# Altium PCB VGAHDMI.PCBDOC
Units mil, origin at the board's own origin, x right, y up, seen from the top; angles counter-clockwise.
Board outline 1870 x 1740 mil, 2 copper layers (Top Layer, Bottom Layer); 8 components, 366 nets, 72 pads, 2 vias.
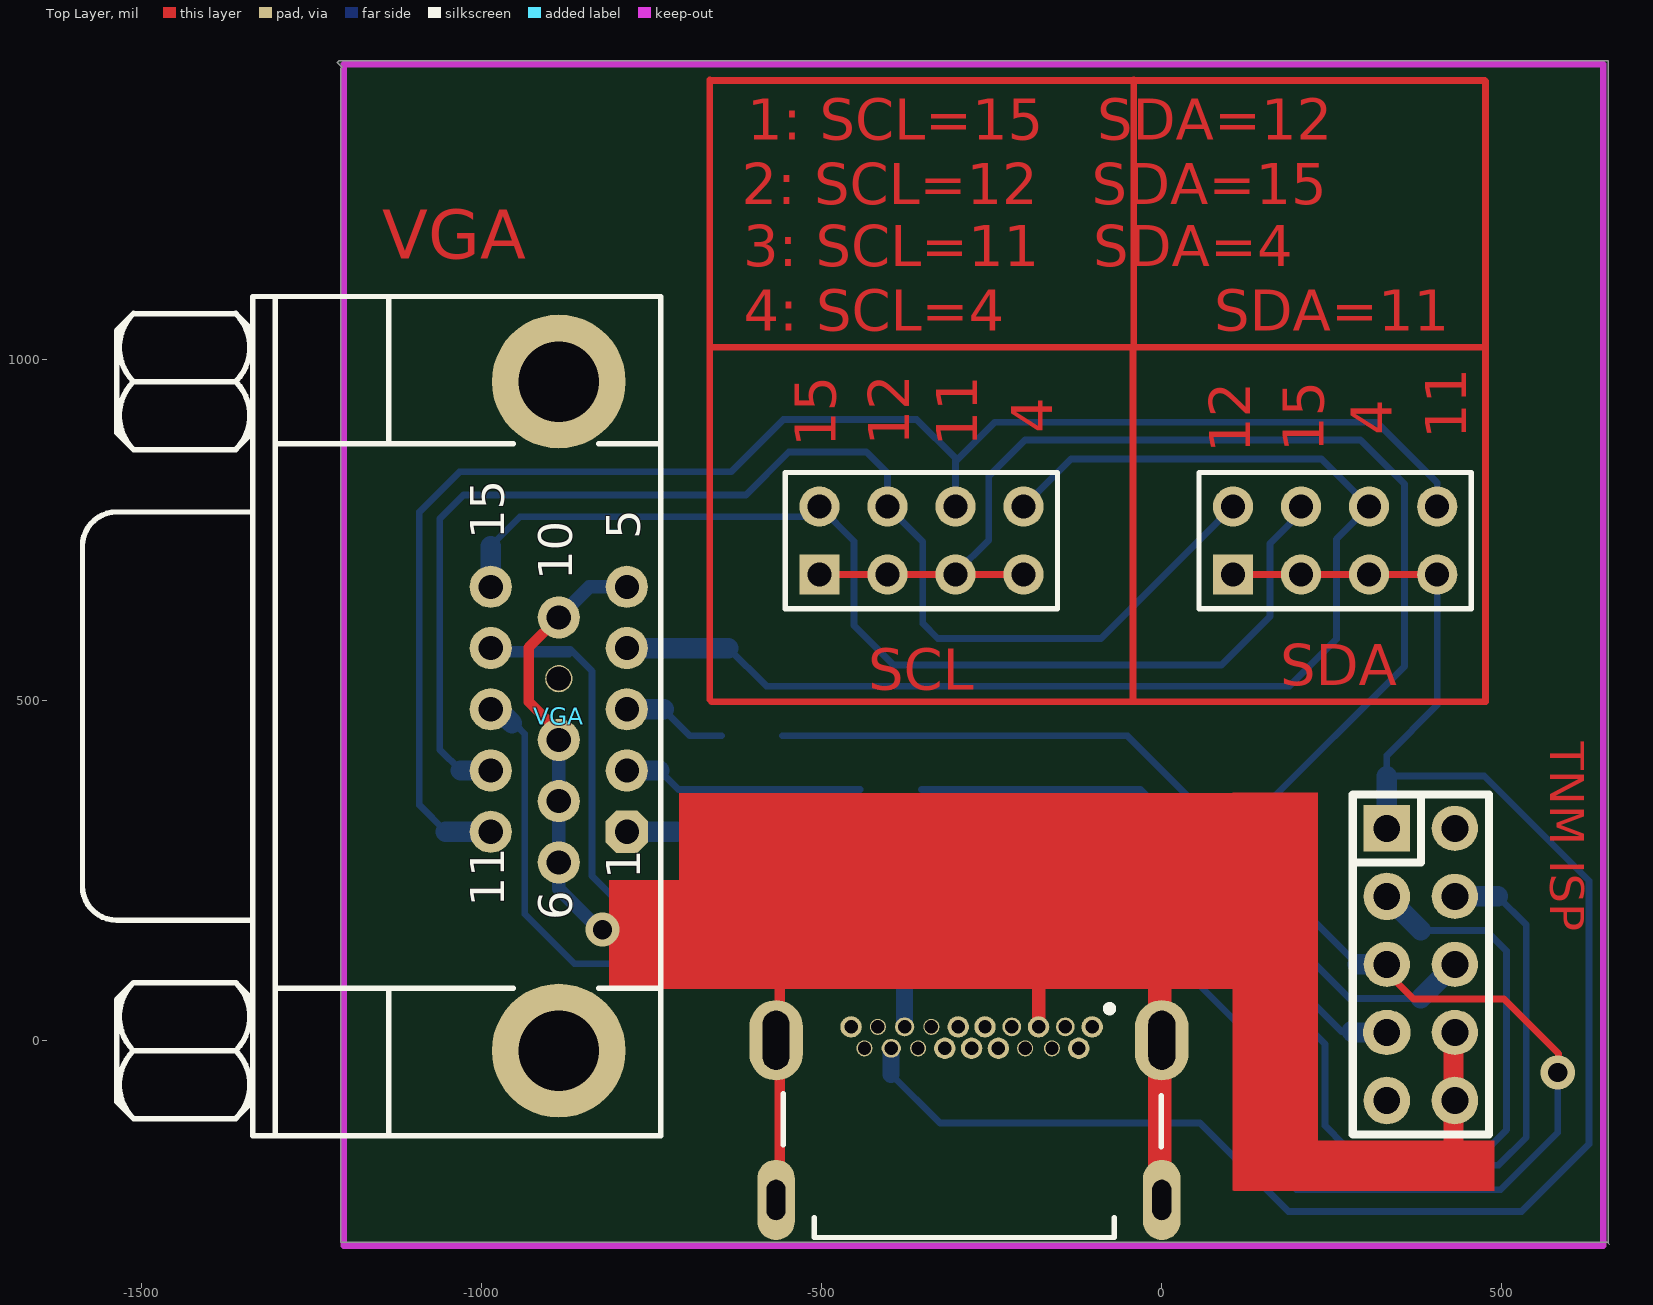
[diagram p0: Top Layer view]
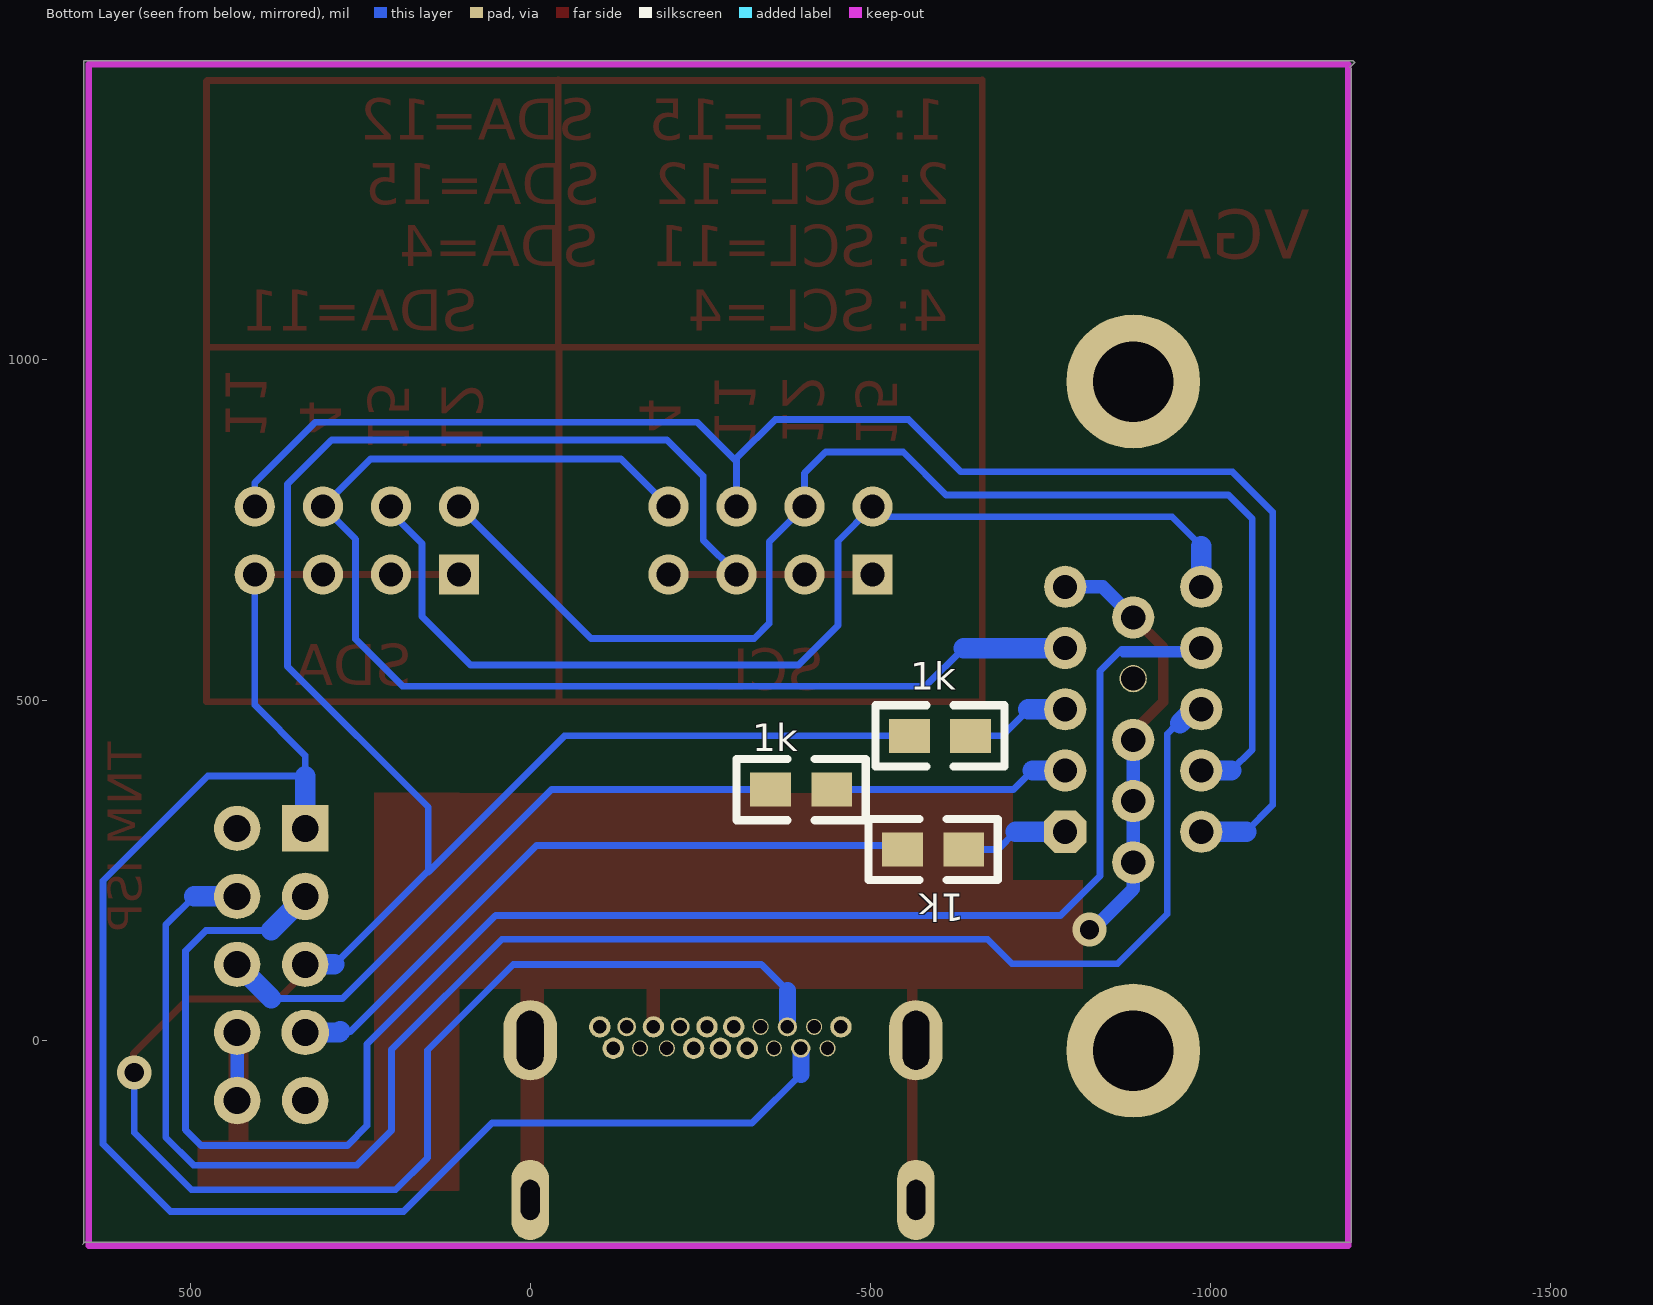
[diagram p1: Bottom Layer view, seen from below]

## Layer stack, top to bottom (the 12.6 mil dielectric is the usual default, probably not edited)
Top Layer: signal copper 1.4
Dielectric: core 12.6, FR-4, Dk 4.8
Bottom Layer: signal copper 1.4

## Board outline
-1212,1437 -1209,1440 656,1440 656,-298 658,-300 655,-297 -1207,-297 -1207,1428 -1205,1430

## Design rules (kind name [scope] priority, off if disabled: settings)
Clearance [All] p1: gap=9
FabricationTestPointUsage TestPointUsage [All] p1: valid=0 allowmultiple=FALSE
FabricationTestpoint Testpoint [(IsPad And (OnTopLayer Or OnBottomLayer))] p1: side=3 testpointundercomponent=TRUE minsize=40 maxsize=100 preferedsize=60 minholesize=0 maxholesize=40 preferedholesize=32 testpointgrid=1 allowsidetop=TRUE allowsidebottom=TRUE usegrid=TRUE gridtolerance=0.01
FanoutControl Fanout_Small [All] p1 off: bgadir=Out bgaviamode=Centered fanoutstyle=Auto fanoutdirection=Alternating viagrid=1 // Protel DXP Scope 1 Expression Was: (CompPinCount < 5)   Fanout_Small (Default Rule)
FanoutControl Fanout_Default [All] p2: bgadir=Out bgaviamode=Centered fanoutstyle=Auto fanoutdirection=Alternating viagrid=1 // Fanout_Default (Default Rule)
FanoutControl Fanout_SOIC [All] p3 off: bgadir=Out bgaviamode=Centered fanoutstyle=Auto fanoutdirection=Alternating viagrid=1 // Protel DXP Scope 1 Expression Was: IsSOIC   Fanout_SOIC (Default Rule)
FanoutControl Fanout_BGA [All] p4 off: bgadir=Out bgaviamode=Centered fanoutstyle=Auto fanoutdirection=Alternating viagrid=1 // Protel DXP Scope 1 Expression Was: IsBGA   Fanout_BGA (Default Rule)
FanoutControl Fanout_LCC [All] p5 off: bgadir=Out bgaviamode=Centered fanoutstyle=Auto fanoutdirection=Alternating viagrid=1 // Protel DXP Scope 1 Expression Was: IsLCC   Fanout_LCC (Default Rule)
PolygonConnect PolygonVia [IsVia] p1: connectstyle=Direct reliefconductorwidth=10 reliefentries=4 polygonreliefangle="90 Angle"
PolygonConnect [All] p2: connectstyle=Relief reliefconductorwidth=10 reliefentries=4 polygonreliefangle="90 Angle"
RoutingCorners [All] p1: cornerstyle=Round minsetback=100 maxsetback=100
RoutingLayers [All] p1: top layer_v5=FALSE bottom layer_v5=FALSE
RoutingVias [All] p1: holewidth=28 width=50 viastyle="Through Hole" minholewidth=28 minwidth=50 maxholewidth=28 maxwidth=50
SilkscreenOverComponentPads [All] p1: minsilkscreentomaskgap=10
SolderMaskExpansion [All] p1: expansion=4
Width [All] p1: maxlimit=150 minlimit=1 preferedwidth=10
18 further rules are at their usual default settings.

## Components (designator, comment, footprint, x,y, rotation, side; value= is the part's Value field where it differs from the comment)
1k "4.7" 0805 -557.25,447.46 r180 bottom
1k "4.7" 0805 -443.25,368.46 r0 bottom
1k "4.7" 0805 -637.25,280.46 r0 bottom
VGA "Comment" DB15FLC -786.25,306.46 r90 top
? "Comment" HDMI/SM0.4-4H19 -290.25,-250.54 r270 top
? "Comment" HDR2X4 -503.25,684.46 r0 top
? "Comment" HDR2X4 104.75,684.46 r0 top
? "2.2k" IDC10 330.75,311.46 r270 top

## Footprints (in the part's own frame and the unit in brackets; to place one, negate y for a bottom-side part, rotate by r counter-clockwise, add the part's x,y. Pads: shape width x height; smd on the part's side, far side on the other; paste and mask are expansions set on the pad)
0805 [mil]
  rect 60x50 smd: 1(0,0) 2(90,0)
  silkscreen extent -50,-45 140,45
DB15FLC [mil]
  oct 62x62 hole 35.43: 1(0,0)
  round 62 hole 35.43: 2(90,0) 3(180,0) 4(270,0) 5(360,0) 6(-45,100) 7(45,100) 8(135,100) 10(315,100) 11(0,200) 12(90,200) 13(180,200) 14(270,200) 15(360,200)
  round 40 hole 35.43: 9(225,100)
  round 196.67 hole 118.33: BO1(-321.67,100) BO2(661.67,100)
  silkscreen extent -447,-50 787,800
HDMI/SM0.4-4H19 [mm] "3168 Series HDMI Type C, Female, Right-Angle, SMT"
  round 0.8 hole 0.5 unplated: 1(-6.864,4.772) 2(-6.064,4.272) 5(-6.864,2.772) 8(-6.064,1.272) 9(-6.864,0.772) 10(-6.064,0.272) 11(-6.864,-0.228) 12(-6.064,-0.728) 19(-6.864,-4.228)
  round 0.7 hole 0.5 unplated: 3(-6.864,3.772) 7(-6.864,1.772)
  round 0.6 hole 0.5 unplated: 4(-6.064,3.272) 6(-6.064,2.272) 13(-6.864,-1.228) 14(-6.064,-1.728) 17(-6.864,-3.228) 18(-6.064,-3.728)
  oval 0.7x0.72 hole 0.5 unplated: 15(-6.864,-2.228) 16(-6.064,-2.728)
  oval 3x2 hole 1 slot 2.2 at 0 deg: MH1(-6.364,-7.028) MH4(-6.364,7.372)
  oval 3x1.4 hole 0.7 slot 1.5 at 0 deg: MH2(-0.404,-7.028) MH3(-0.404,7.372)
  silkscreen extent -7.67,-6.76 1,7.35
HDR2X4 [mm] "Connector; Header; 4x2 Position"
  rect 1.5x1.5 hole 0.9: 1(0,0)
  round 1.5 hole 0.9: 2(0,2.54) 3(2.54,0) 4(2.54,2.54) 5(5.08,0) 6(5.08,2.54) 7(7.62,0) 8(7.62,2.54)
  silkscreen extent -1.27,-1.27 8.89,3.81
IDC10 [mil]
  rect 68x68 hole 39.37: 1(0,0)
  oval 66x68 hole 39.37: 2(0,100) 4(100,100) 5(200,0) 6(200,100) 8(300,100)
  oval 70x68 hole 39.37: 3(100,0) 9(400,0) 10(400,100)
  oval 66x70 hole 39.37: 7(300,0)
  silkscreen extent -50,-50 450,150

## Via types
v1: diameter 50, hole 28, Top Layer to Bottom Layer, 2 vias

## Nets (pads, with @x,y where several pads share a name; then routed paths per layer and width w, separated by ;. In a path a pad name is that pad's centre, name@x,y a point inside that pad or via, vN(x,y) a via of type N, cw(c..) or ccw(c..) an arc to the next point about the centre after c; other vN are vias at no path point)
5V: 
12+: 
+3.3V: 
+5: 
AD0: 
AD1: 
AD2: 
AD3: 
AD4: 
AD5: 
AD6: 
AD7: 
ALE: 
AREF: 
BLUE: 1k.2@-647.25,447.46 VGA.3 | length 155.2
  Bottom Layer w10: -732.25,486.46 -693.25,447.46 1k.2@-647.25,447.46
  Bottom Layer w30: VGA.3 -732.25,486.46
CANA: 
CANEN: 
CANH: 
CANL: 
CASE: 
COMP7: 
COMP10: 
COMP14: 
COMP15: 
CTL0: 
CTL1: 
CTL2: 
D12X1: 
D12X2: 
DEBUG: 
DELYF: 
DLYEN: 
DM: 
DONE: 
DP: 
EMPTY: 
FD0: 
FD1: 
FD2: 
FD3: 
FD4: 
FD5: 
FD6: 
FD7: 
FIFOADD0: 
FULL: 
G: 1k.1@-443.25,368.46 VGA.2 | length 354.6
  Bottom Layer w10: -738.25,396.46 -710.25,368.46 1k.1@-443.25,368.46
  Bottom Layer w30: VGA.2 -738.25,396.46
GND: ?.5@-181.1,19.69 ?.8@430.75,11.46 ?.10@430.75,-88.54 ?.MH1 ?.MH2 ?.MH3 ?.MH4 VGA.5 VGA.6 VGA.7 VGA.8 VGA.10 | length 962.7
  Top Layer w10: VGA.8 VGA.8@-886.25,453.46
  Top Layer w15: VGA.8@-886.25,453.46 -930.25,497.46 -930.25,577.46 VGA.10
  Top Layer w20: ?.5@-181.1,19.69 -181.1,76.26
  Top Layer w30: 428.75,-174.54 ?.8@428.75,-11.54
  Bottom Layer w10: v1@-828.25,164.46 v1@-821.25,164.46
  Bottom Layer w20: VGA.8 VGA.7 VGA.6 -886.25,222.46 v1@-828.25,164.46 ; VGA.10 -841.25,666.46 VGA.5 ; ?.10@430.75,-88.54 ?.8@430.75,11.46
  other v1: -822.25,162.46
GNDISO: 
GREEN: 1k.2@-353.25,368.46 ?.6@430.75,111.46 | length 932.9
  Bottom Layer w10: 1k.2@-353.25,368.46 -31.25,368.46 275.75,61.46 381.75,61.46
  Bottom Layer w30: 380.75,61.46 ?.6@430.75,111.46
H: ?.4@430.75,211.46 VGA.13 | length 2504.2
  Bottom Layer w10: VGA.13 VGA.13@-973.46,486.46 ; -948,462 -936.25,450.25 -936.25,185.46 -863.25,112.46 -708.25,112.46 -672.25,148.46 41.75,148.46 203.75,-13.54 203.75,-132.54 254.75,-183.54 494.75,-183.54 535.75,-142.54 535.75,169.46 493.75,211.46
  Bottom Layer w30: VGA.13@-979.25,490.25 -955,466 ; ?.4@430.75,211.46 493.75,211.46
HSYNC: 
IGNITION: 
ISPCLKI: 
ISPEN: 
ISPHIN1: 
ISPIN1: 
ISPIN6: 
ISPOUT1: 
ISPOUT4: 
ISPOUT6: 
ISPPDII: 
ISPRST: 
ISPSCK: 
ISPSDI: 
ISPSDO: 
LED: 
MCLR: 
MCU_CLK: 
MCU_RESET: 
MISO: 
MOSI: 
N01: 
N02: 
N03: 
N04: 
N05: 
N5: 
N06: 
N6: 
N07: 
N7: 
N08: 
N8: 
N09: 
N10: 
N11: 
N12: 
N13: 
N14: 
N15: 
N16: 
N17: 
N18: 
N19: 
N20: 
N21: 
N23: 
N25: 
N26: 
N27: 
N28: 
N29: 
N30: 
N31: 
N32: 
N33: 
N34: 
N35: 
N36: 
N37: 
N38: 
N39: 
N40: 
N41: 
N42: 
N43: 
N44: 
N45: 
N46: 
N47: 
N48: 
N49: 
N66: 
NC4: 
NewNet: 
O4: 
O5: 
O6: 
O7: 
O11: 
O12: 
O13: 
OB1: 
OB2: 
OB3: 
OB4: 
OB5: 
OB6: 
OB7: 
OB8: 
OB9: 
OB10: 
OB11: 
OB12: 
OB13: 
OB14: 
OB15: 
OBD1: 
OBD2: 
OBD3: 
OBD6: 
OBD6S: 
OBD7: 
OBD9: 
OBD10: 
OBD11: 
OBD12: 
OBD13: 
OBD14: 
OBD14S: 
OBD15: 
OE: 
P0: 
P1: 
P2: 
P3: 
P04: 
P4: ?.6@304.75,784.46 ?.8@-203.25,784.46 VGA.4 | length 1875.6
  Bottom Layer w10: -637.25,576.46 -581.25,520.46 187.75,520.46 256.75,589.46 256.75,736.46 304.75,784.46 234.75,854.46 -133.25,854.46 ?.8@-203.25,784.46
  Bottom Layer w30: VGA.4 -637.25,576.46
P05: 
P5: 
P6: 
P7: 
P11: ?.6@-303.25,784.46 ?.8@404.75,784.46 VGA.11 | length 2295
  Bottom Layer w10: -1052.25,306.46 -1091.25,345.46 -1091.25,776.46 -1032.25,835.46 -633.25,835.46 -556.25,912.46 -360.25,912.46 -303.25,855.46 -303.25,850.46 ; ?.6@-303.25,784.46 -303.25,850.46 ; ?.8@404.75,784.46 404.75,819.46 315.75,908.46 -245.25,908.46 -303.25,850.46
  Bottom Layer w30: -1052.25,306.46 VGA.11
P12: ?.2@104.75,784.46 ?.4@-403.25,784.46 VGA.12 | length 1926.3
  Bottom Layer w10: -1030.25,396.46 -1061.25,427.46 -1061.25,766.46 -1026.25,801.46 -611.25,801.46 -548.25,864.46 -434.25,864.46 -403.25,833.46 -403.25,784.46 -351.25,732.46 -351.25,612.46 -329.25,590.46 -89.25,590.46 ?.2@104.75,784.46
  Bottom Layer w30: -1030.25,396.46 VGA.12
P15: ?.2@-503.25,784.46 ?.4@204.75,784.46 VGA.15 | length 1608.6
  Bottom Layer w10: -986.25,726.46 -943.25,769.46 -518.25,769.46 -503.25,784.46 -452.25,733.46 -452.25,609.46 -394.25,551.46 87.75,551.46 159.22,622.94 159.22,729.99 204.75,775.52 ?.4@204.75,784.46
  Bottom Layer w30: VGA.15 -986.25,726.46
PA1: 
PC0: 
PC1: 
PDI: 
PDIH: 
PIN1: 
PIN1HB: 
PIN1LB: 
PIN1SB: 
PIN2: 
PIN2H: 
PIN2HB: 
PIN2LB: 
PIN2SB: 
PIN3: 
PIN4: 
PIN4LB: 
PIN4S: 
PIN4SB: 
PIN5: 
PIN6: 
PIN7: 
PIN8: 
PIN9: 
PIN10: 
PIN11: 
PIN12: 
PIN13: 
PIN14: 
PIN15: 
PIN16: 
PIN17: 
PIN18: 
PIN19: 
PIN20: 
PIN21: 
PIN22: 
PIN23: 
PIN24: 
PIN25: 
PIN26: 
PIN27: 
PIN28: 
PIN29: 
PIN30: 
PIN31: 
PIN31H: 
PIN31HB: 
PIN31I: 
PIN31L: 
PIN32: 
PIN33: 
PIN34: 
PIN35: 
PIN36: 
PIN37: 
PIN38: 
PIN39: 
PIN40: 
PIN41: 
PIN42: 
PIN43: 
PIN44: 
PIN45: 
PIN46: 
PIN47: 
PIN48: 
PKTEND: 
PO4: 
PO5: 
PROGRAM: 
PULH: 
PULL: 
PWM1: 
PWM2: 
PWML1: 
PWML2: 
PWMOUT1: 
PWMOUT2: 
R: 1k.1@-637.25,280.46 VGA.1 | length 159.8
  Bottom Layer w10: -713.25,306.46 -687.25,280.46 1k.1@-637.25,280.46
  Bottom Layer w30: VGA.1 -713.25,306.46
RED: 1k.2@-547.25,280.46 ?.7@330.75,11.46 | length 984.9
  Bottom Layer w10: 1k.2@-532.25,286.46 -9.25,286.46 264.21,13 279,13
  Bottom Layer w30: 279,13 280.54,11.46 ?.7@338.75,11.46
RELCAN: 
RESET: 
RLCAN: 
RST: 
RST1: 
RST2: 
RST_SEL: 
RST_SELN: 
RSTF: 
RX: 
RX_K: 
RXD: 
RXD1: 
RXI: 
RXIN: 
RXK: 
SCK: 
SCK1: 
SCKF: 
SCKH: 
SCKI: 
SCL1: 
SCL_BLU: 1k.1@-557.25,447.46 ?.1@-503.25,684.46 ?.3@-403.25,684.46 ?.5@330.75,111.46 ?.5@-303.25,684.46 ?.7@-203.25,684.46 ?.15 | length 4537.6
  Top Layer w10: ?.1@-503.25,684.46 -403.25,684.46 -303.25,684.46 ?.7@-203.25,684.46 ; ?.5@330.75,111.46 330.75,99.46 369.75,60.46 502.75,60.46 582.95,-19.74 v1@582.95,-50.69
  Bottom Layer w10: 1k.1@-557.25,447.46 -50.25,447.46 149.75,247.46 149.75,342.46 356.75,549.46 356.75,817.46 291.75,882.46 -201.25,882.46 -254.25,829.46 -254.25,735.46 -303.25,686.46 ?.5@-303.25,684.46 ; -377.95,73.05 -339.68,111.31 24.95,111.31 150.95,-14.69 150.95,-172.69 197.95,-219.69 497.95,-219.69 581.95,-135.69 v1@581.95,-56.33 ; 148.14,251.07 287.75,111.46
  Bottom Layer w25: ?.15 -377.95,73.05
  Bottom Layer w30: 287.75,111.46 ?.5@339.75,111.46
  other v1: 581.95,-47.69
SDA: ?.1@104.75,684.46 ?.1@330.75,311.46 ?.3@204.75,684.46 ?.5@304.75,684.46 ?.7@404.75,684.46 ?.16 | length 2672.5
  Top Layer w10: ?.1@104.75,684.46 204.75,684.46 ?.7@408.75,684.46
  Bottom Layer w10: -397.64,-50.09 -326.05,-121.69 55.95,-121.69 185.95,-251.69 528.95,-251.69 627.95,-152.69 627.95,234.46 473.95,388.46 330.75,388.46 330.75,418.46 404.75,492.46 ?.7@404.75,684.46 ; ?.1@330.75,311.46 ?.1@350.75,331.46
  Bottom Layer w25: -397.64,-50.09 ?.16
  Bottom Layer w30: ?.1@330.75,311.46 330.75,388.46
SDA1: 
SDA-B: 
SDI: 
SDI1: 
sdin: 
SDO: 
SDO_PRG: 
SDOCAN: 
SELECT: 
SS: 
Switch: 
TCK: 
TDI: 
TDO: 
TMS: 
TX: 
TXD: 
TXD2: 
V: ?.3@330.75,211.46 VGA.14 | length 2643.7
  Bottom Layer w10: -871.34,567.46 -958.25,567.46 -967.25,576.46 VGA.14 -984.25,574.46 -869.25,574.46 -837.25,542.46 -837.25,241.46 -779.25,183.46 50.75,183.46 239.75,-5.54 239.75,-125.54 268.75,-154.54 483.75,-154.54 506.75,-131.54 506.75,131.46 476.75,161.46 380.75,161.46 ; ?.3@330.75,211.46 ?.3@331.75,211.46
  Bottom Layer w30: ?.3@330.75,211.46 380.75,161.46
VADJ: 
VC: 
VCC: 
VCC3.3: 
VCC5: ?.2@430.75,311.46
VCCM: 
VDRV: 
VI: 
VIN: 
VIN1: 
VIN2: 
VP: 
VPP: 
VPP1: 
VREG: 
VSYNC: 
X1: 
X2: 
Z1: 
Z2: 
Z3: 
Z4: 
Z5: 
Z6: 
Z7: 
Z8: 
Z9: 
Z10: 
Z11: 
Z12: 
Z13: 
Z14: 
Z15: 
Z16: 
Z17: 
Z18: 
Z19: 
Z20: 
Z21: 
Z22: 
Z23: 
Z24: 
Z25: 
Z26: 
Z27: 
Z28: 
Z29: 
Z30: 
Z31: 
Z32: 
Z33: 
Z34: 
Z35: 
Z36: 
Z37: 
Z38: 
Z39: 
Z40: 
Z41: 
Z42: 
Z43: 
Z44: 
Z45: 
Z46: 
Z47: 
Z48: 
pads on no net: ?.1@-102.36,19.69 ?.2@-122.05,-11.81 ?.3@-141.73,19.69 ?.4@-161.42,-11.81 ?.6@-200.79,-11.81 ?.7@-220.47,19.69 ?.8@-240.16,-11.81 ?.9 ?.10@-279.53,-11.81 ?.11 ?.12 ?.13 ?.14 ?.17 ?.18 ?.19 VGA.9 VGA.BO1 VGA.BO2
copper on no net: | length 6162.5
  Top Layer w10: -664.25,1021.46 -664.25,500.46 -661.25,497.46 475.75,497.46 475.75,1021.46 ; -664.25,1411.46 -664.25,1017.46 -663.25,1018.46 475.75,1018.46 475.75,1409.46 474.75,1410.46 -663.25,1410.46 ; -42.25,500.46 -42.25,1018.46 -41.25,1019.46 -41.25,1411.46

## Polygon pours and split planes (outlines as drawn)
GND on Top Layer "Top Layer-GND 4" (hatched 90Degree grid 20 track 10, pour order 1014): -2481.23,792.02
VCC3.3 on Top Layer "Top Layer-VCC3.0 2" (hatched 90Degree grid 8 track 8, remove dead copper, pour order 1013): 911.77,3759.91
VCC3.3 on Top Layer "Top Layer-VCC3.0" (hatched 90Degree grid 8 track 8, remove dead copper, pour order 1011): 532.77,4298.91
GND on Top Layer "Top Layer-GND 3" (hatched 90Degree grid 8 track 8, remove dead copper, pour order 1010): -1102.23,2999.91
GND on Top Layer "Top Layer-GND 2" (hatched 90Degree grid 8 track 8, remove dead copper, pour order 1008): -891.23,1986.91
GND on Bottom Layer "Bottom Layer-GND 2" (hatched 45Degree grid 15 track 8, remove dead copper, pour order 1023): 1354.77,684.91
N26 on Bottom Layer "Bottom Layer-N26 1" (hatched 90Degree grid 8 track 8, remove dead copper, pour order 1022): 140.77,5039.91
no net on Bottom Layer "Bottom Layer-L6" (hatched 90Degree grid 8 track 8, remove dead copper, pour order 1021): -1987.23,2633.91

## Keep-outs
Keep-Out Layer:
  lines w10: -1202.25,-302 -1202.25,1434.46 648.75,1434.46 648.75,-302 -1202.25,-302

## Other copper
Top Layer:
  rectangle net GND: -569.05,-222.69 -554.05,122.31
  rectangle net GND: -20.05,-225.69 13.95,121.31
  rectangle net GND: 105.75,-221.54 488.75,-147.54
  rectangle net GND: -709.25,164.46 109.75,363.46
  rectangle net GND: 103.75,-220.54 229.75,364.46
  rectangle net GND: -812.25,75.46 116.75,235.46
  text "1: SCL=15   SDA=12" at -609.25,1323.46 h60
  text "2: SCL=12   SDA=15" at -617.25,1228.46 h60
  text "3: SCL=11   SDA=4" at -615.25,1137.46 h60
  text "4: SCL=4" at -614.25,1042.46 h60
  text "SDA=11" at 76.75,1042.46 h60
  text "4" at -161.25,892.46 h60 r90
  text "4" at 337.75,889.46 h60 r90
  text "11" at 447.75,883.46 h60 r90
  text "12" at -371.25,873.46 h60 r90
  text "11" at -271.25,872.46 h60 r90
  text "15" at -479.25,871.46 h60 r90
  text "15" at 237.75,864.46 h60 r90
  text "12" at 129.75,862.46 h60 r90
  text "SDA" at 173.75,521.46 h60
  text "SCL" at -431.25,515.46 h60
  text "TNM ISP" at 571,439 h50 r270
